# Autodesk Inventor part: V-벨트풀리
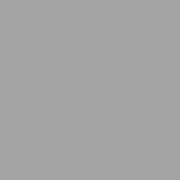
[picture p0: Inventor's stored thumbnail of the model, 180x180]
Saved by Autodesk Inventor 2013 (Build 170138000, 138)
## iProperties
Created: 2015-02
Part Number: V-벨트풀리
Material: 일반
Document SubType Name: Modeling
Designer: Administrator
Density: 1 g/cm^3
Author: Administrator
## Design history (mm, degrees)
